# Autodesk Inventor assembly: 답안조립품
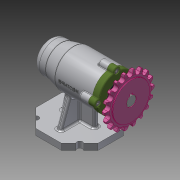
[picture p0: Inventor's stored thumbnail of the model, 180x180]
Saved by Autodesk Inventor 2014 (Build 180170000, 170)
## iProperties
Created: 2021-01
Part Number: 답안조립품
Document SubType Name: Assembly
Designer: kh
Author: kh
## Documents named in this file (12)
- C:\Users\kh\Desktop\710106V1021\답안조립품.iam
- C:\Users\kh\Desktop\710106V1021\본체.ipt
- C:\Users\kh\Desktop\710106V1021\멈춤나사 M3.ipt
- C:\Users\kh\Desktop\710106V1021\베어링 6004.ipt
- C:\Users\kh\Desktop\710106V1021\베어링 51202.ipt
- C:\Users\kh\Desktop\710106V1021\볼트 M4.ipt
- C:\Users\kh\Desktop\710106V1021\스프로킷.ipt
- C:\Users\kh\Desktop\710106V1021\어댑터슬리브.ipt
- C:\Users\kh\Desktop\710106V1021\오일 실.ipt
- C:\Users\kh\Desktop\710106V1021\축.ipt
- C:\Users\kh\Desktop\710106V1021\커버.ipt
- C:\Users\kh\Desktop\710106V1021\키 5 x 5 x 14.ipt
